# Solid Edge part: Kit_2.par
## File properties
Author: ahadarics
Last saved by: ahadarics
Revision: 76
Sűrűség: 0,000 kg/m^3
Pontosság: 0,990
Username: ahadarics
Dokumentum tartalom típus: 0
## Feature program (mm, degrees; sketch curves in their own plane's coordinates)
base feature "unnamed BaseFeature 1"
sketch for "unnamed Protrusion 1" #1 plane through (0, 22, 0) normal (0, 1, 0) x-axis (0, 0, -1)
  arc centre (0, 0) radius 8 from (5.2915, -6) to (-5.2915, -6) cw
  line (-5.2915, -6) -> (5.2915, -6)
sketch for "unnamed Protrusion 1" #2 plane through (0, 22, 0) normal (0, 1, 0) x-axis (0, 0, -1)
  line (-5.2915, 6) -> (5.2915, 6)
extrude "unnamed Protrusion 1" add to key point along -normal
thread "unnamed Thread 1"
sketch for "unnamed Cutout 1" #1 plane through (0, 22, 0) normal (0, 1, 0) x-axis (0, 0, -1)
  line (-5.2915, -6) -> (5.2915, -6)
  arc centre (0, 0) radius 8 from (5.2915, -6) to (-5.2915, -6) cw
sketch for "unnamed Cutout 1" #2 plane through (0, 22, 0) normal (0, 1, 0) x-axis (0, 0, -1)
  line (-5.2915, 6) -> (5.2915, 6)
extrude "unnamed Cutout 1" cut finite 17 along -normal
chamfer "Letörés_1" setback 1
sketch for "Furat_4" plane through (0, -0.5, 8.5) normal (0, 0, 1) x-axis (0, 1, 0)
  hole centre (0, 0) bore radius 2.067
hole "Furat_4" nominal diameter 5 finite  ThreadDepth = 4.5 mm
chamfer "Letörés_2" setback 0.5
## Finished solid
Body 1: solid body, 33 faces, 74 edges, 42 vertices.
  Faces by surface: plane 14, cylinder 11, cone 8
  Edges by curve: line 34, circle 32, intersection 4, spline 4
Bounding box of the edges (mm): 19.000 x 28.500 x 18.100, from (-9.5, -6.5, -9.5) to (9.5, 22, 8.6).
Cylindrical faces by radius (mm): R2.06 x1, R2.067 x1, R3 x1, R6.85 x2, R8 x4, R8.6 x1, R9.5 x1
Conical faces (half-angle, radius in mm at the cone's reference point): 45 deg R2.567 x1, 45 deg R3.1 x2, 45 deg R8 x2, 59 deg R1.0335 x1, 60 deg R7.425 x2
Planar faces by outward normal: +x 1, +y 8, +z 2, -x 1, -y 2
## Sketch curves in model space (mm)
arc centre (0, 22, 0) radius 8 from (6, 22, -5.2915) through (7.9967, 22, 0.2312) to (6, 22, 5.2915)
line (6, 22, 5.2915) -> (6, 22, -5.2915)
arc centre (0, 22, 0) radius 8 from (-6, 22, 5.2915) through (-7.9967, 22, -0.2312) to (-6, 22, -5.2915)
line (-6, 22, 5.2915) -> (-6, 22, -5.2915)
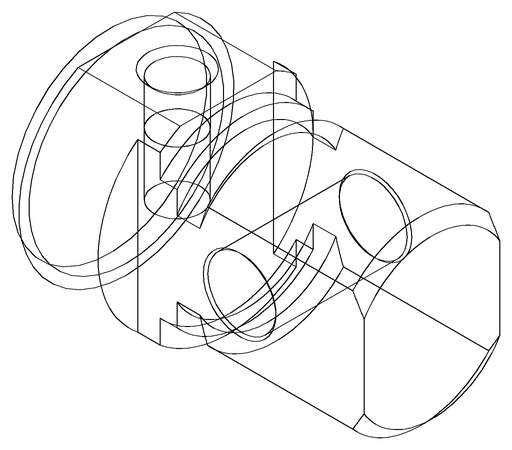
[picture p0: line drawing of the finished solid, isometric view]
